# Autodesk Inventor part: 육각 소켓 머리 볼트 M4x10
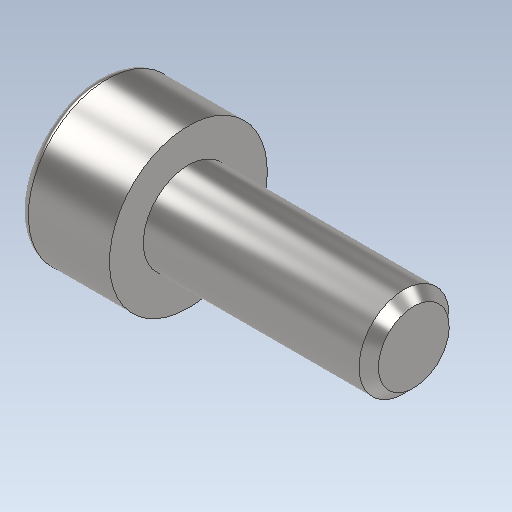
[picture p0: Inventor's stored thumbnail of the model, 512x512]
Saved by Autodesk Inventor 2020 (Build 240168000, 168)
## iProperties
Created: 2024-07
Part Number: 육각 소켓 머리 볼트 M4x10
Material: 강철, 연강
Description: 6각머리 태핑 나사
Document SubType Name: Modeling
Designer: oem
Density: 7.85 g/cm^3
Appearance: 기본값
Mass: 2.0343 g
Surface Area: 3.06255 cm^2
Volume: 0.259146 cm^3
Sending System: Autodesk Inventor 2025
Preprocessor: ST-DEVELOPER v20
Author: jhkim
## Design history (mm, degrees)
feature "Solid1"
node "솔리드1"
